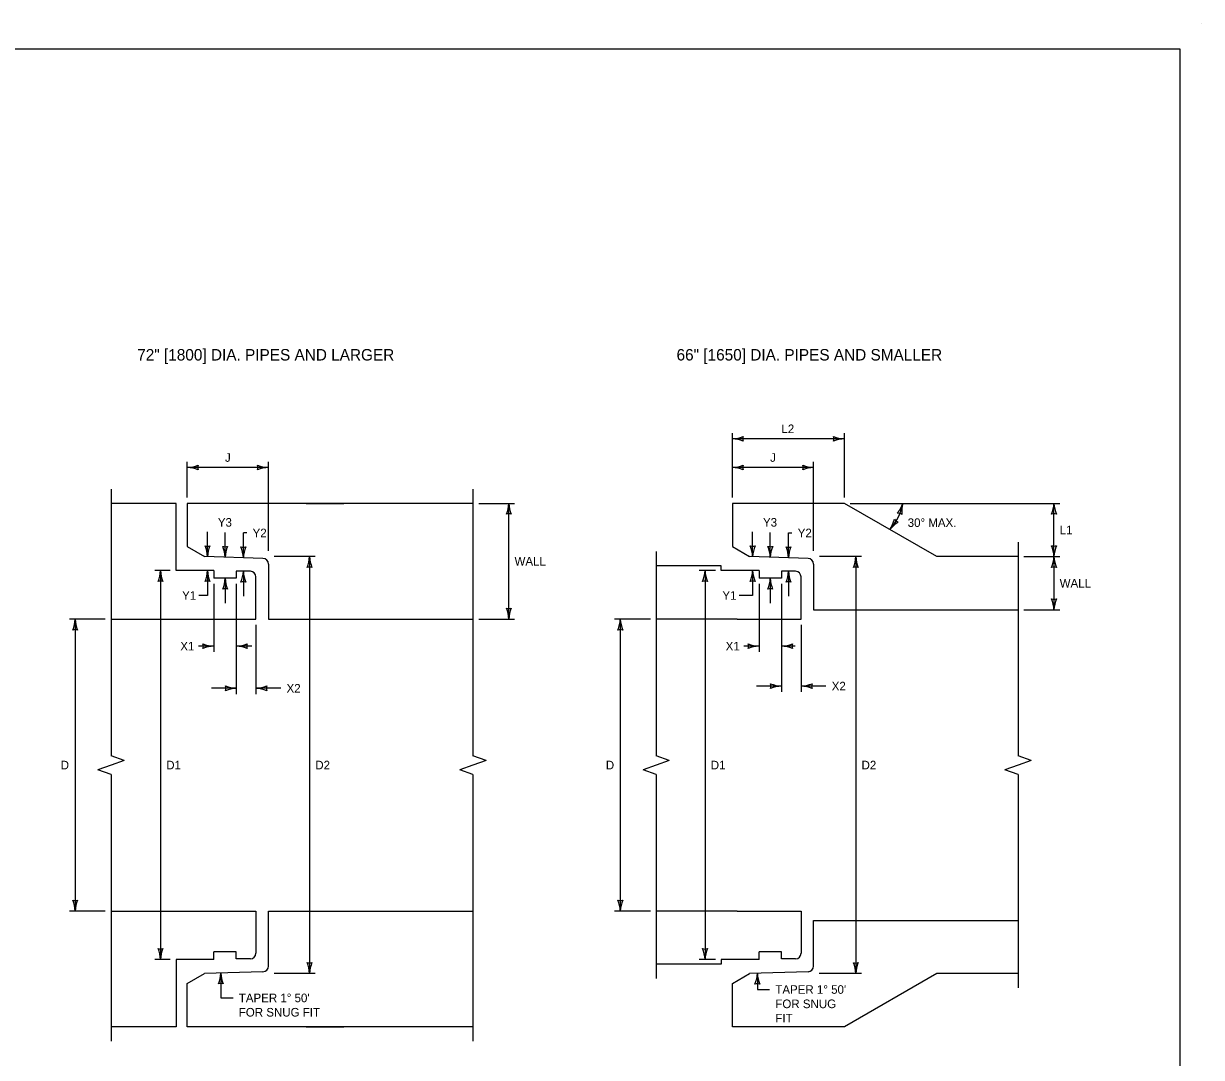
# Model space of a CAD drawing. Extents: x 49991.4 to 50021, y 49987.6 to 50011.4.
# Drawn here: x 50008.69 to 50016.9, y 49991.96 to 49999.18 of the extents above; entities that cross this region are included whole.
import ezdxf

# ---------------------------------------------------------------- set-up
doc = ezdxf.new("R2010")
doc.units = 0
for name, color, linetype in [('Level 1', 7, 'Continuous'), ('Level 2', 7, 'Continuous'), ('Level 3', 7, 'Continuous'), ('Level 6', 7, 'Continuous')]:
    doc.layers.add(name, color=color, linetype=linetype)

msp = doc.modelspace()

# ---------------------------------------------------------------- linework, layer by layer
at = {"layer": 'Level 1'}
for p, q in [((50016.9001, 49999.1756), (50016.9001, 49999.1756)), ((50009.7525, 49995.829), (50009.2993, 49995.829)), ((50009.7525, 49995.3599), (50009.7525, 49995.829)), ((50011.822, 49995.829), (50009.8304, 49995.829)), ((50009.8304, 49995.829), (50009.8304, 49995.5272)), ((50010.659, 49995.829), (50010.9215, 49995.829)), ((50014.412, 49995.829), (50013.6303, 49995.829)), ((50013.6303, 49995.829), (50013.6303, 49995.5272)), ((50015.0552, 49995.4577), (50014.412, 49995.829)), ((50009.8304, 49995.5272), (50009.9507, 49995.4577)), ((50013.6303, 49995.5272), (50013.7507, 49995.4577)), ((50010.3576, 49995.4447), (50009.9507, 49995.4577)), ((50010.3967, 49995.4056), (50010.3967, 49995.0217)), ((50013.5524, 49995.393), (50013.0992, 49995.393)), ((50013.5524, 49995.393), (50013.4586, 49995.393)), ((50013.5524, 49995.3599), (50013.5524, 49995.393)), ((50014.1576, 49995.4447), (50013.7507, 49995.4577)), ((50014.1967, 49995.4056), (50014.1967, 49995.0864)), ((50015.6219, 49995.4577), (50015.0552, 49995.4577)), ((50010.0164, 49995.3599), (50009.7525, 49995.3599)), ((50010.0164, 49995.3599), (50010.0164, 49995.3066)), ((50010.1727, 49995.3066), (50010.0164, 49995.3066)), ((50010.1727, 49995.3555), (50010.1727, 49995.3066)), ((50010.2705, 49995.3555), (50010.1727, 49995.3555)), ((50010.3095, 49995.0217), (50010.3095, 49995.3164)), ((50013.8163, 49995.3599), (50013.5524, 49995.3599)), ((50013.8163, 49995.3599), (50013.8163, 49995.3066)), ((50013.9727, 49995.3066), (50013.8163, 49995.3066)), ((50013.9727, 49995.3555), (50013.9727, 49995.3066)), ((50014.0704, 49995.3555), (50013.9727, 49995.3555)), ((50014.1095, 49995.0217), (50014.1095, 49995.3164)), ((50014.1967, 49995.0864), (50015.6219, 49995.0864)), ((50009.2993, 49995.0217), (50010.3095, 49995.0217)), ((50010.3967, 49995.0217), (50011.822, 49995.0217)), ((50013.6631, 49995.0217), (50013.0992, 49995.0217)), ((50013.6631, 49995.0217), (50014.1095, 49995.0217)), ((50009.2993, 49992.9854), (50010.3095, 49992.9854)), ((50010.3095, 49992.9854), (50010.3095, 49992.6907)), ((50010.3967, 49992.6015), (50010.3967, 49992.9854)), ((50010.3967, 49992.9854), (50011.822, 49992.9854)), ((50013.6631, 49992.9854), (50013.0992, 49992.9854)), ((50013.6631, 49992.9854), (50014.1095, 49992.9854)), ((50014.1095, 49992.9854), (50014.1095, 49992.6907)), ((50014.1967, 49992.6015), (50014.1967, 49992.9207)), ((50014.1967, 49992.9207), (50015.6219, 49992.9207)), ((50010.0164, 49992.6472), (50010.0164, 49992.7005)), ((50010.1727, 49992.7005), (50010.0164, 49992.7005)), ((50010.1727, 49992.6516), (50010.1727, 49992.7005)), ((50013.8163, 49992.6472), (50013.8163, 49992.7005)), ((50013.9727, 49992.7005), (50013.8163, 49992.7005)), ((50013.9727, 49992.6516), (50013.9727, 49992.7005)), ((50009.7525, 49992.6472), (50009.7525, 49992.1781)), ((50010.0164, 49992.6472), (50009.7525, 49992.6472)), ((50010.2705, 49992.6516), (50010.1727, 49992.6516)), ((50013.5524, 49992.6141), (50013.0992, 49992.6141)), ((50013.5524, 49992.6141), (50013.4586, 49992.6141)), ((50013.5524, 49992.6472), (50013.5524, 49992.6141)), ((50013.8163, 49992.6472), (50013.5524, 49992.6472)), ((50014.0704, 49992.6516), (50013.9727, 49992.6516)), ((50009.8304, 49992.4799), (50009.9507, 49992.5494)), ((50010.3576, 49992.5624), (50009.9507, 49992.5494)), ((50013.6303, 49992.4799), (50013.7507, 49992.5494)), ((50014.1576, 49992.5624), (50013.7507, 49992.5494)), ((50015.0552, 49992.5494), (50014.412, 49992.1781)), ((50015.6219, 49992.5494), (50015.0552, 49992.5494)), ((50009.8304, 49992.1781), (50009.8304, 49992.4799)), ((50013.6303, 49992.1781), (50013.6303, 49992.4799)), ((50009.7525, 49992.1781), (50009.2993, 49992.1781)), ((50011.822, 49992.1781), (50009.8304, 49992.1781)), ((50010.659, 49992.1781), (50010.9215, 49992.1781)), ((50014.412, 49992.1781), (50013.6303, 49992.1781))]:
    msp.add_line(p, q, dxfattribs=at)
msp.add_lwpolyline([(49999.3835, 49998.9992), (50016.7501, 49998.9992), (50016.7501, 49987.7988), (49999.3835, 49987.7988)], close=True, dxfattribs=at)
for centre, start, end in [((50010.3576, 49995.4056), 0, 90), ((50014.1576, 49995.4056), 0, 90), ((50010.2705, 49995.3164), 0, 90), ((50014.0704, 49995.3164), 0, 90), ((50010.2705, 49992.6907), 270, 0), ((50014.0704, 49992.6907), 270, 0), ((50010.3576, 49992.6015), 270, 0), ((50014.1576, 49992.6015), 270, 0)]:
    msp.add_arc(centre, 0.0391, start, end, dxfattribs=at)
at = {"layer": 'Level 3'}
for p, q in [((50013.6303, 49995.8759), (50013.6303, 49996.319)), ((50014.412, 49995.869), (50014.412, 49996.319)), ((50014.412, 49996.279), (50013.6303, 49996.279)), ((50009.8304, 49995.869), (50009.8304, 49996.119)), ((50010.3971, 49995.4977), (50010.3971, 49996.119)), ((50013.6303, 49995.869), (50013.6303, 49996.1259)), ((50014.197, 49995.4977), (50014.197, 49996.119)), ((50010.3971, 49996.079), (50009.8304, 49996.079)), ((50014.197, 49996.079), (50013.6303, 49996.079)), ((50011.862, 49995.829), (50012.112, 49995.829)), ((50012.072, 49995.0217), (50012.072, 49995.829)), ((50014.452, 49995.829), (50015.9119, 49995.829)), ((50015.8719, 49995.4577), (50015.8719, 49995.829)), ((50009.9716, 49995.4571), (50009.9716, 49995.6305)), ((50010.0946, 49995.4531), (50010.0946, 49995.6265)), ((50013.7715, 49995.4571), (50013.7715, 49995.6305)), ((50013.8945, 49995.4531), (50013.8945, 49995.6265)), ((50010.2461, 49995.6225), (50010.2216, 49995.6225)), ((50010.2216, 49995.4491), (50010.2216, 49995.6225)), ((50014.0215, 49995.6225), (50014.046, 49995.6225)), ((50014.0215, 49995.4491), (50014.0215, 49995.6225)), ((50010.7231, 49995.4577), (50010.4371, 49995.4577)), ((50010.6831, 49995.4577), (50010.6831, 49992.5504)), ((50014.5309, 49995.4577), (50014.237, 49995.4577)), ((50014.4909, 49995.4577), (50014.4909, 49992.5494)), ((50015.6619, 49995.4577), (50015.9119, 49995.4577)), ((50015.8719, 49995.4577), (50015.8719, 49995.0864)), ((50009.7125, 49995.3599), (50009.6042, 49995.3599)), ((50009.6442, 49995.3599), (50009.6442, 49992.6472)), ((50009.9716, 49995.3599), (50009.9716, 49995.1865)), ((50010.0946, 49995.3066), (50010.0946, 49995.1332)), ((50010.2216, 49995.3555), (50010.2216, 49995.1821)), ((50013.5124, 49995.3599), (50013.4, 49995.3599)), ((50013.44, 49995.3599), (50013.44, 49992.6472)), ((50013.7715, 49995.3599), (50013.7715, 49995.1865)), ((50013.8945, 49995.3066), (50013.8945, 49995.1332)), ((50014.0215, 49995.3555), (50014.0215, 49995.1821)), ((50010.0164, 49995.2666), (50010.0164, 49994.833)), ((50010.1727, 49995.2666), (50010.1727, 49994.5389)), ((50013.8163, 49995.2666), (50013.8163, 49994.793)), ((50013.9727, 49995.2666), (50013.9727, 49994.5143)), ((50009.9716, 49995.1865), (50009.9116, 49995.1865)), ((50013.7715, 49995.1865), (50013.6777, 49995.1865)), ((50015.6619, 49995.0864), (50015.9119, 49995.0864)), ((50009.2593, 49995.0217), (50009.0093, 49995.0217)), ((50009.0493, 49995.0217), (50009.0493, 49992.9854)), ((50010.3095, 49994.9817), (50010.3095, 49994.5389)), ((50011.862, 49995.0217), (50012.112, 49995.0217)), ((50013.0592, 49995.0217), (50012.8092, 49995.0217)), ((50012.8492, 49995.0217), (50012.8492, 49992.9854)), ((50014.1095, 49994.9817), (50014.1095, 49994.5143)), ((50010.0164, 49994.833), (50009.9082, 49994.833)), ((50010.0164, 49994.833), (50010.0164, 49994.793)), ((50010.2808, 49994.833), (50010.1727, 49994.833)), ((50013.8163, 49994.833), (50013.7098, 49994.833)), ((50014.0689, 49994.833), (50013.9727, 49994.833)), ((50010.1727, 49994.5389), (50009.9993, 49994.5389)), ((50010.1727, 49994.5389), (50010.1727, 49994.4989)), ((50010.4829, 49994.5389), (50010.3095, 49994.5389)), ((50010.3095, 49994.5389), (50010.3095, 49994.4989)), ((50013.9727, 49994.5543), (50013.7993, 49994.5543)), ((50014.2829, 49994.5543), (50014.1095, 49994.5543)), ((50009.0493, 49992.9854), (50009.0093, 49992.9854)), ((50009.2593, 49992.9854), (50009.0493, 49992.9854)), ((50013.0592, 49992.9854), (50012.8092, 49992.9854)), ((50009.7125, 49992.6472), (50009.6042, 49992.6472)), ((50013.5124, 49992.6472), (50013.4, 49992.6472)), ((50010.0648, 49992.5531), (50010.0648, 49992.3797)), ((50010.7231, 49992.5504), (50010.4368, 49992.5504)), ((50013.8049, 49992.5512), (50013.8049, 49992.4383)), ((50014.5309, 49992.5494), (50014.2349, 49992.5494)), ((50010.0648, 49992.4221), (50010.0648, 49992.4221)), ((50013.8049, 49992.4383), (50013.89, 49992.4383)), ((50010.0648, 49992.3797), (50010.1499, 49992.3797))]:
    msp.add_line(p, q, dxfattribs=at)
for centre, radius, start, end in [((50013.6188, 49996.5117), 0.233, 272.82731, 292.07716), ((50013.7585, 49996.279), 0.0548, 162.13882, 197.86118), ((50014.4212, 49996.5012), 0.2223, 247.45601, 267.63952), ((50014.2838, 49996.279), 0.0548, 342.13882, 17.86118), ((50013.6212, 49996.0569), 0.2223, 67.45601, 87.63952), ((50014.4235, 49996.0463), 0.233, 92.82731, 112.07716), ((50009.8189, 49996.3117), 0.233, 272.82731, 292.07716), ((50009.8213, 49995.8569), 0.2223, 67.45601, 87.63952), ((50009.9586, 49996.079), 0.0548, 162.13882, 197.86118), ((50010.4063, 49996.3012), 0.2223, 247.45601, 267.63952), ((50010.2689, 49996.079), 0.0548, 342.13882, 17.86118), ((50010.4086, 49995.8463), 0.233, 92.82731, 112.07716), ((50013.6188, 49996.3117), 0.233, 272.82731, 292.07716), ((50013.6212, 49995.8569), 0.2223, 67.45601, 87.63952), ((50013.7585, 49996.079), 0.0548, 162.13882, 197.86118), ((50014.2062, 49996.3012), 0.2223, 247.45601, 267.63952), ((50014.0688, 49996.079), 0.0548, 342.13882, 17.86118), ((50014.2085, 49995.8463), 0.233, 92.82731, 112.07716), ((50011.8499, 49995.8382), 0.2223, 337.45601, 357.63952), ((50012.3047, 49995.8405), 0.233, 182.82731, 202.07716), ((50014.4621, 49995.8898), 0.3607, 320.65907, 347.28264), ((50014.6071, 49995.9004), 0.2223, 321.08229, 341.2658), ((50015.0442, 49995.7744), 0.233, 166.45359, 185.70344), ((50015.6498, 49995.8382), 0.2223, 337.45601, 357.63952), ((50016.1046, 49995.8405), 0.233, 182.82731, 202.07716), ((50012.072, 49995.7008), 0.0548, 72.13882, 107.86118), ((50014.5334, 49995.774), 0.233, 326.80676, 346.05661), ((50014.8038, 49995.7501), 0.0548, 216.11827, 251.84063), ((50014.7815, 49995.706), 0.0548, 55.7651, 91.48746), ((50015.8719, 49995.7008), 0.0548, 72.13882, 107.86118), ((50014.9026, 49995.5084), 0.2223, 121.43546, 141.61897), ((50009.9716, 49995.5853), 0.0548, 252.13882, 287.86118), ((50009.7389, 49995.4456), 0.233, 2.82731, 22.07716), ((50010.1938, 49995.4479), 0.2223, 157.45601, 177.63952), ((50010.0946, 49995.5813), 0.0548, 252.13882, 287.86118), ((50009.8619, 49995.4416), 0.233, 2.82731, 22.07716), ((50010.3168, 49995.444), 0.2223, 157.45601, 177.63952), ((50010.2216, 49995.5773), 0.0548, 252.13882, 287.86118), ((50009.9889, 49995.4376), 0.233, 2.82731, 22.07716), ((50010.4438, 49995.4399), 0.2223, 157.45601, 177.63952), ((50013.7715, 49995.5853), 0.0548, 252.13882, 287.86118), ((50013.5388, 49995.4456), 0.233, 2.82731, 22.07716), ((50013.9937, 49995.4479), 0.2223, 157.45601, 177.63952), ((50013.8945, 49995.5813), 0.0548, 252.13882, 287.86118), ((50013.6618, 49995.4416), 0.233, 2.82731, 22.07716), ((50014.1167, 49995.444), 0.2223, 157.45601, 177.63952), ((50014.0215, 49995.5773), 0.0548, 252.13882, 287.86118), ((50013.7888, 49995.4376), 0.233, 2.82731, 22.07716), ((50014.2437, 49995.4399), 0.2223, 157.45601, 177.63952), ((50015.8719, 49995.5859), 0.0548, 252.13882, 287.86118), ((50015.6392, 49995.4462), 0.233, 2.82731, 22.07716), ((50016.0941, 49995.4486), 0.2223, 157.45601, 177.63952), ((50010.461, 49995.4669), 0.2223, 337.45601, 357.63952), ((50010.6831, 49995.3295), 0.0548, 72.13882, 107.86118), ((50010.9158, 49995.4692), 0.233, 182.82731, 202.07716), ((50014.2688, 49995.4669), 0.2223, 337.45601, 357.63952), ((50014.4909, 49995.3295), 0.0548, 72.13882, 107.86118), ((50014.7236, 49995.4692), 0.233, 182.82731, 202.07716), ((50015.6498, 49995.4669), 0.2223, 337.45601, 357.63952), ((50015.8719, 49995.3295), 0.0548, 72.13882, 107.86118), ((50016.1046, 49995.4692), 0.233, 182.82731, 202.07716), ((50009.4221, 49995.3691), 0.2223, 337.45601, 357.63952), ((50009.8769, 49995.3714), 0.233, 182.82731, 202.07716), ((50009.7495, 49995.3691), 0.2223, 337.45601, 357.63952), ((50010.2043, 49995.3714), 0.233, 182.82731, 202.07716), ((50009.8725, 49995.3158), 0.2223, 337.45601, 357.63952), ((50010.3273, 49995.3181), 0.233, 182.82731, 202.07716), ((50009.9995, 49995.3647), 0.2223, 337.45601, 357.63952), ((50010.4543, 49995.367), 0.233, 182.82731, 202.07716), ((50013.2179, 49995.3691), 0.2223, 337.45601, 357.63952), ((50013.6727, 49995.3714), 0.233, 182.82731, 202.07716), ((50013.5494, 49995.3691), 0.2223, 337.45601, 357.63952), ((50014.0042, 49995.3714), 0.233, 182.82731, 202.07716), ((50013.6724, 49995.3158), 0.2223, 337.45601, 357.63952), ((50014.1272, 49995.3181), 0.233, 182.82731, 202.07716), ((50013.7994, 49995.3647), 0.2223, 337.45601, 357.63952), ((50014.2542, 49995.367), 0.233, 182.82731, 202.07716), ((50009.6442, 49995.2317), 0.0548, 72.13882, 107.86118), ((50009.9716, 49995.2317), 0.0548, 72.13882, 107.86118), ((50010.0946, 49995.1784), 0.0548, 72.13882, 107.86118), ((50010.2216, 49995.2273), 0.0548, 72.13882, 107.86118), ((50013.44, 49995.2317), 0.0548, 72.13882, 107.86118), ((50013.7715, 49995.2317), 0.0548, 72.13882, 107.86118), ((50013.8945, 49995.1784), 0.0548, 72.13882, 107.86118), ((50014.0215, 49995.2273), 0.0548, 72.13882, 107.86118), ((50015.8719, 49995.2146), 0.0548, 252.13882, 287.86118), ((50015.6392, 49995.0749), 0.233, 2.82731, 22.07716), ((50016.0941, 49995.0773), 0.2223, 157.45601, 177.63952), ((50012.072, 49995.1499), 0.0548, 252.13882, 287.86118), ((50011.8393, 49995.0102), 0.233, 2.82731, 22.07716), ((50012.2942, 49995.0126), 0.2223, 157.45601, 177.63952), ((50008.8272, 49995.0309), 0.2223, 337.45601, 357.63952), ((50009.282, 49995.0332), 0.233, 182.82731, 202.07716), ((50012.6271, 49995.0309), 0.2223, 337.45601, 357.63952), ((50013.0819, 49995.0332), 0.233, 182.82731, 202.07716), ((50009.0493, 49994.8935), 0.0548, 72.13882, 107.86118), ((50012.8492, 49994.8935), 0.0548, 72.13882, 107.86118), ((50010.0256, 49995.0552), 0.2223, 247.45601, 267.63952), ((50009.8882, 49994.833), 0.0548, 342.13882, 17.86118), ((50010.0279, 49994.6003), 0.233, 92.82731, 112.07716), ((50010.1612, 49995.0657), 0.233, 272.82731, 292.07716), ((50010.1636, 49994.6109), 0.2223, 67.45601, 87.63952), ((50010.3009, 49994.833), 0.0548, 162.13882, 197.86118), ((50013.8255, 49995.0552), 0.2223, 247.45601, 267.63952), ((50013.6881, 49994.833), 0.0548, 342.13882, 17.86118), ((50013.8278, 49994.6003), 0.233, 92.82731, 112.07716), ((50013.9612, 49995.0657), 0.233, 272.82731, 292.07716), ((50013.9636, 49994.6109), 0.2223, 67.45601, 87.63952), ((50014.1009, 49994.833), 0.0548, 162.13882, 197.86118), ((50010.1819, 49994.7611), 0.2223, 247.45601, 267.63952), ((50010.0445, 49994.5389), 0.0548, 342.13882, 17.86118), ((50010.298, 49994.7716), 0.233, 272.82731, 292.07716), ((50010.4377, 49994.5389), 0.0548, 162.13882, 197.86118), ((50013.9819, 49994.7765), 0.2223, 247.45601, 267.63952), ((50013.8445, 49994.5543), 0.0548, 342.13882, 17.86118), ((50014.098, 49994.787), 0.233, 272.82731, 292.07716), ((50014.2377, 49994.5543), 0.0548, 162.13882, 197.86118), ((50010.1842, 49994.3062), 0.233, 92.82731, 112.07716), ((50010.3004, 49994.3168), 0.2223, 67.45601, 87.63952), ((50013.9842, 49994.3216), 0.233, 92.82731, 112.07716), ((50014.1004, 49994.3322), 0.2223, 67.45601, 87.63952), ((50009.0493, 49993.1136), 0.0548, 252.13882, 287.86118), ((50008.8166, 49992.9739), 0.233, 2.82731, 22.07716), ((50009.2715, 49992.9763), 0.2223, 157.45601, 177.63952), ((50012.8492, 49993.1136), 0.0548, 252.13882, 287.86118), ((50012.6165, 49992.9739), 0.233, 2.82731, 22.07716), ((50013.0714, 49992.9763), 0.2223, 157.45601, 177.63952), ((50009.6442, 49992.7754), 0.0548, 252.13882, 287.86118), ((50009.4115, 49992.6357), 0.233, 2.82731, 22.07716), ((50009.8664, 49992.6381), 0.2223, 157.45601, 177.63952), ((50013.44, 49992.7754), 0.0548, 252.13882, 287.86118), ((50013.2073, 49992.6357), 0.233, 2.82731, 22.07716), ((50013.6622, 49992.6381), 0.2223, 157.45601, 177.63952), ((50010.6831, 49992.6786), 0.0548, 252.13882, 287.86118), ((50010.4504, 49992.5389), 0.233, 2.82731, 22.07716), ((50010.9053, 49992.5413), 0.2223, 157.45601, 177.63952), ((50014.4909, 49992.6776), 0.0548, 252.13882, 287.86118), ((50014.2582, 49992.5379), 0.233, 2.82731, 22.07716), ((50014.7131, 49992.5403), 0.2223, 157.45601, 177.63952), ((50009.8427, 49992.5622), 0.2223, 337.45601, 357.63952), ((50010.2975, 49992.5646), 0.233, 182.82731, 202.07716), ((50013.5828, 49992.5603), 0.2223, 337.45601, 357.63952), ((50014.0376, 49992.5626), 0.233, 182.82731, 202.07716), ((50010.0648, 49992.4249), 0.0548, 72.13882, 107.86118), ((50013.8049, 49992.4229), 0.0548, 72.13882, 107.86118)]:
    msp.add_arc(centre, radius, start, end, dxfattribs=at)
at = {"layer": 'Level 6'}
for p, q in [((50009.2993, 49995.929), (50009.2993, 49994.0684)), ((50011.822, 49995.929), (50011.822, 49994.0684)), ((50015.6219, 49995.5577), (50015.6219, 49994.0684)), ((50013.0992, 49995.493), (50013.0992, 49994.0684)), ((50009.3907, 49994.036), (50009.2993, 49994.0684)), ((50011.9134, 49994.036), (50011.822, 49994.0684)), ((50013.1906, 49994.036), (50013.0992, 49994.0684)), ((50015.7133, 49994.036), (50015.6219, 49994.0684)), ((50009.2993, 49994.0036), (50009.2079, 49993.9712)), ((50009.3907, 49994.036), (50009.2993, 49994.0036)), ((50011.822, 49994.0036), (50011.7306, 49993.9712)), ((50011.9134, 49994.036), (50011.822, 49994.0036)), ((50013.0992, 49994.0036), (50013.0078, 49993.9712)), ((50013.1906, 49994.036), (50013.0992, 49994.0036)), ((50015.6219, 49994.0036), (50015.5305, 49993.9712)), ((50015.7133, 49994.036), (50015.6219, 49994.0036)), ((50009.2993, 49993.9388), (50009.2079, 49993.9712)), ((50009.2993, 49993.9388), (50009.2993, 49992.0781)), ((50011.822, 49993.9388), (50011.7306, 49993.9712)), ((50011.822, 49993.9388), (50011.822, 49992.0781)), ((50013.0992, 49993.9388), (50013.0078, 49993.9712)), ((50013.0992, 49993.9388), (50013.0992, 49992.5141)), ((50015.6219, 49993.9388), (50015.5305, 49993.9712)), ((50015.6219, 49993.9388), (50015.6219, 49992.4494))]:
    msp.add_line(p, q, dxfattribs=at)

# ---------------------------------------------------------------- texts
at = {"layer": 'Level 2'}
for s, height, p in [('72" [1800] DIA. PIPES AND LARGER', 0.08, (50009.4818, 49996.8253)), ('66" [1650] DIA. PIPES AND SMALLER ', 0.08, (50013.2413, 49996.8253)), ('L2', 0.06, (50013.9723, 49996.319)), ('J', 0.06, (50010.0934, 49996.119)), ('J', 0.06, (50013.8933, 49996.119)), ('Y3', 0.06, (50010.044, 49995.6665)), ('Y3', 0.06, (50013.8439, 49995.6665)), ('30° MAX.', 0.06, (50014.8525, 49995.6644)), ('Y2', 0.06, (50010.2861, 49995.5925)), ('Y2', 0.06, (50014.086, 49995.5925)), ('L1', 0.06, (50015.9119, 49995.6134)), ('WALL', 0.06, (50012.112, 49995.3954)), ('WALL', 0.06, (50015.9119, 49995.242)), ('Y1', 0.06, (50009.7947, 49995.1565)), ('Y1', 0.06, (50013.5608, 49995.1565)), ('X1', 0.06, (50009.782, 49994.803)), ('X1', 0.06, (50013.5836, 49994.803)), ('X2', 0.06, (50010.5229, 49994.5089)), ('X2', 0.06, (50014.3229, 49994.5243)), ('D', 0.06, (50008.9486, 49993.9736)), ('D1', 0.06, (50009.6842, 49993.9736)), ('D2', 0.06, (50010.7231, 49993.9736)), ('D', 0.06, (50012.7485, 49993.9736)), ('D1', 0.06, (50013.48, 49993.9736)), ('D2', 0.06, (50014.5309, 49993.9736)), ("TAPER 1° 50'", 0.06, (50013.93, 49992.4083)), ("TAPER 1° 50' ", 0.06, (50010.1899, 49992.3497)), ('FOR SNUG', 0.06, (50013.93, 49992.3083)), ('FOR SNUG FIT', 0.06, (50010.1899, 49992.2497)), ('FIT', 0.06, (50013.93, 49992.2083))]:
    msp.add_text(s, height=height, dxfattribs=at).set_placement(p)

doc.saveas('drawing.dxf')
